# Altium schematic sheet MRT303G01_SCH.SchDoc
size A4
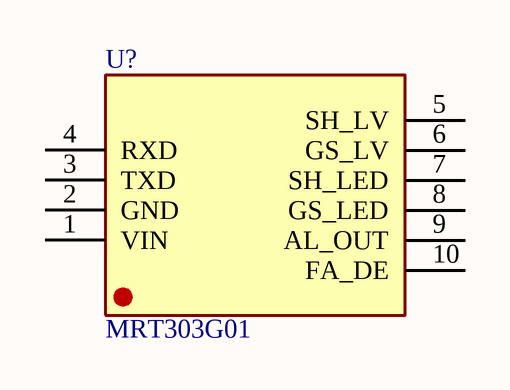
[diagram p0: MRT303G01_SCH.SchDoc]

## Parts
U?  MRT303G01  [SO-8]

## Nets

Not connected (* = marked no-connect by the designer): U? 1(VIN) 2(GND) 3(TXD) 4(RXD) 5(SH_LV) 6(GS_LV) 7(SH_LED) 8(GS_LED) 9(AL_OUT) 10(FA_DE)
